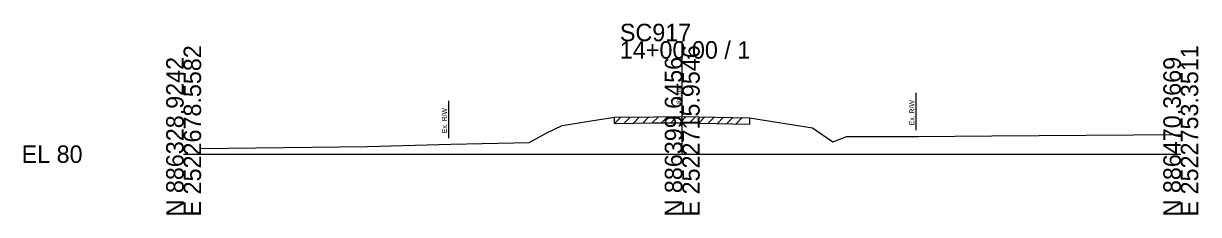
# Model space of a CAD drawing. Extents: x -26 to 218, y -10 to 12021.
# Drawn here: x -25.7 to 162.8, y 10990.3 to 11021 of the extents above; entities that cross this region are included whole.
import ezdxf

# ---------------------------------------------------------------- set-up
doc = ezdxf.new("R2010")
doc.units = 0
for name, color, linetype in [('RD_GPK_XS_Cell', 7, 'Continuous'), ('RD_XS_ExGround', 7, 'Continuous'), ('RD_XS_ExPaveRet', 7, 'Continuous'), ('RD_XS_ExRW', 7, 'Continuous'), ('RD_XS_TX_Elev_EX', 7, 'Continuous')]:
    doc.layers.add(name, color=color, linetype=linetype)

msp = doc.modelspace()

# ---------------------------------------------------------------- linework, layer by layer
at = {"layer": 'RD_GPK_XS_Cell'}
for p, q in [((80, 11000), (80, 11018.13)), ((0, 11000), (80, 11000)), ((80, 11000), (160, 11000))]:
    msp.add_line(p, q, dxfattribs=at)
at = {"layer": 'RD_XS_ExGround'}
for p, q in [((60.73, 11004.58), (65.4, 11005.33)), ((65.4, 11005.33), (69.16, 11005.93)), ((69.16, 11005.93), (75.49, 11006)), ((75.49, 11006), (80.07, 11006.04)), ((80.07, 11006.04), (90.82, 11005.83)), ((90.82, 11005.83), (100.88, 11004.22)), ((55.42, 11001.89), (58.29, 11003.41)), ((58.29, 11003.41), (60.73, 11004.58)), ((100.88, 11004.22), (104.15, 11002)), ((104.15, 11002), (106.39, 11002.81)), ((106.39, 11002.81), (117.89, 11002.85)), ((117.89, 11002.85), (129.67, 11002.92)), ((129.67, 11002.92), (159.99, 11003.13)), ((2.68, 11000.93), (29.5, 11001.25)), ((29.5, 11001.25), (42.87, 11001.58)), ((42.87, 11001.58), (55.42, 11001.89))]:
    msp.add_line(p, q, dxfattribs=at)
at = {"layer": 'RD_XS_ExPaveRet'}
for p, q in [((69.16, 11004.93), (70.17, 11005.94)), ((69.16, 11004.93), (69.16, 11005.93)), ((69.16, 11004.93), (75.49, 11005)), ((70.66, 11004.95), (71.67, 11005.96)), ((72.16, 11004.97), (73.17, 11005.98)), ((73.66, 11004.98), (74.67, 11006)), ((75.16, 11005), (76.17, 11006.01)), ((75.49, 11005), (80.07, 11005.04)), ((76.66, 11005.02), (77.67, 11006.02)), ((78.16, 11005.03), (79.17, 11006.04)), ((79.66, 11005.04), (80.65, 11006.03)), ((80.07, 11005.04), (90.82, 11004.83)), ((81.16, 11005.02), (82.14, 11006)), ((82.66, 11004.99), (83.64, 11005.97)), ((84.16, 11004.96), (85.14, 11005.94)), ((85.66, 11004.93), (86.64, 11005.91)), ((87.16, 11004.9), (88.14, 11005.89)), ((88.66, 11004.87), (89.64, 11005.86)), ((90.82, 11005.83), (90.82, 11004.83))]:
    msp.add_line(p, q, dxfattribs=at)
at = {"layer": 'RD_XS_ExRW'}
for p, q in [((42.5, 11008.57), (42.5, 11002.57)), ((117.5, 11009.85), (117.5, 11003.85)), ((117.5, 11009.85), (117.5, 11003.85))]:
    msp.add_line(p, q, dxfattribs=at)

# ---------------------------------------------------------------- texts
at = {"layer": 'RD_GPK_XS_Cell'}
for s, p in [('SC917', (70, 11018.13)), ('14+00.00 / 1', (70, 11015.33)), ('EL 80', (-26, 10998.6))]:
    msp.add_text(s, height=2.8, dxfattribs=at).set_placement(p)
for s, p in [('E 2522678.5582', (2.8, 10990)), ('E 2522715.9546', (82.8, 10990)), ('E 2522753.3511', (162.8, 10990)), ('N 886328.9242', (0, 10990)), ('N 886399.6456', (80, 10990)), ('N 886470.3669', (160, 10990))]:
    msp.add_text(s, height=2.8, rotation=90, dxfattribs=at).set_placement(p)
at = {"layer": 'RD_XS_ExRW'}
for p in [(117.25, 11004.63), (117.25, 11004.63), (42.25, 11003.36)]:
    msp.add_text('Ex. R/W ', height=0.8, rotation=90, dxfattribs=at).set_placement(p)
at = {"layer": 'RD_XS_TX_Elev_EX'}
msp.add_text('86.04', height=0.8, rotation=90, dxfattribs=at).set_placement((79.9, 11008.04))

doc.saveas('drawing.dxf')
